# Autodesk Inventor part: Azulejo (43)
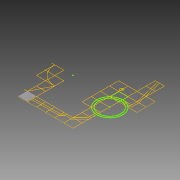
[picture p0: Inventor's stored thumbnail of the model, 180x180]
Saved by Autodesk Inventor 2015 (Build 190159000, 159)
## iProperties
Created: 2015-04
Part Number: Azulejo (43)
Material: Genérico
Document SubType Name: Modeling
Designer: Felipe
Density: 1 g/cm^3
Appearance: Padrão
Author: Felipe
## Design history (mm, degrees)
sketch "Sketch1"
  geometry: L1 (-1510, -7490)-(-1510, -6010); L2 (-3010, -1490)-(-3010, -10); L3 (-2990, 10)-(-1510, 10); L4 (-1510, -10)-(-2990, -10); L5 (-1510, -1490)-(-1510, -10); L6 (-1490, -10)-(-1490, -1490); L7 (-1490, -1490)-(-10, -1490); L8 (-10, -1510)-(-1490, -1510); L9 (-10, -2990)-(-10, -1510); L10 (-10, -5990)-(-10, -4510); L11 (-1490, -7490)-(-10, -7490); L12 (4490, -6010)-(3010, -6010); L13 (10, -1510)-(10, -2990); L14 (10, -3010)-(10, -4490); L15 (10, -4510)-(10, -5990); L16 (10, -5990)-(1490, -5990); L17 (1490, -6010)-(10, -6010); L18 (10, -7490)-(1490, -7490); L19 (1510, -5990)-(2990, -5990); L20 (2990, -6010)-(1510, -6010); L21 (1510, -7490)-(2990, -7490); L22 (4490, 1510)-(4490, 2990); L23 (4490, 10)-(4490, 1490); L24 (4490, -1490)-(4490, -10); L25 (4490, -2990)-(4490, -1510); L26 (3010, -5990)-(4490, -5990); L27 (3010, -7490)-(4490, -7490); L28 (4510, 3010)-(5990, 3010); L29 (5990, 2990)-(4510, 2990); L30 (4510, 2990)-(4510, 1510); L31 (4510, 1510)-(5990, 1510); L32 (5990, 1510)-(5990, 1740.185); L33 (5990, 1760.2)-(5990, 2259.8); L34 (5990, 2279.815)-(5990, 2990); L35 (5990, 1490)-(4510, 1490); L36 (4510, 1490)-(4510, 10); L37 (4510, 10)-(5990, 10); L38 (5990, 10)-(5990, 1490); L39 (5975.983, -10)-(4510, -10); L40 (4510, -10)-(4510, -1490); L41 (5990, -1510)-(5782.897, -1510); L42 (5782.897, -1510)-(5688.66, -1510); L43 (5668.66, -1510)-(5482.895, -1510); L44 (5482.895, -1510)-(5388.656, -1510); L45 (5368.656, -1510)-(4510, -1510); L46 (4510, -1510)-(4510, -2990); L47 (4510, -2990)-(5975.983, -2990); L48 (5990, -2975.728)-(5990, -2837.377); L49 (5990, -2837.377)-(5990, -2536.247); L50 (5990, -2500.476)-(5990, -2317.632); L51 (5990, -2317.632)-(5990, -1510); L52 (5990, -3010)-(4510, -3010); L53 (5990, -4490)-(5990, -3010); L54 (4510, -5990)-(5990, -5990); L55 (5990, -5990)-(5990, -4510); L56 (4510, -7490)-(5990, -7490); L57 (5990, -7490)-(5990, -6310); L58 (5990, -6290)-(5990, -6010); L59 (7490, 4510)-(7490, 5990); L60 (6010, 3010)-(7490, 3010); L61 (7490, 3010)-(7490, 4490); L62 (7490, 2990)-(6010, 2990); L63 (6010, 2990)-(6010, 2279.815); L64 (6010, 2259.8)-(6010, 1760.2)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; A1 r 250 centre (6000, 2010) between (5990, 2259.8) and (5990, 1760.2); A2 r 250 centre (6000, 2010) between (6010, 1760.2) and (6010, 2259.8); A3 r 270 centre (6000, 2010) between (5990, 2279.815) and (5990, 1740.185); A4 r 270 centre (6000, 2010) between (6010, 1740.185) and (6010, 2279.815); A5 r 3010.017 centre (0, 0) between (-1490, -2615.358) and (-346.554, -2990); A6 r 2990.017 centre (0, 0) between (-1490, -2592.316) and (-10, -2990); A7 r 3010.017 centre (0, 0) between (-2603.863, -1510) and (-1510, -2603.863); A8 r 2990.017 centre (0, 0) between (-2580.717, -1510) and (-1510, -2580.717); A9 r 3010.017 centre (0, 0) between (-2990, -346.554) and (-2615.358, -1490); A10 r 2990.017 centre (0, 0) between (-2990, -10) and (-2592.316, -1490); A11 r 2131.367 centre (7500, -1500) between (7490, 631.344) and (6010, 24.017); A12 r 2131.367 centre (7500, -1500) between (5975.983, -10) and (5368.656, -1490); A13 r 2131.367 centre (7500, -1500) between (5368.656, -1510) and (5975.983, -2990); A14 r 2131.367 centre (7500, -1500) between (6010, -3024.017) and (7190, -3608.703); A15 r 1831.367 centre (7500, -1500) between (7490.321, 331.342) and (6463.753, 10); A16 r 1831.367 centre (7500, -1500) between (7489.976, 331.34) and (6010, -435.196); A17 r 1831.367 centre (7500, -1500) between (5990, -463.753) and (5668.66, -1490); A18 r 1831.367 centre (7500, -1500) between (5668.66, -1510) and (5990, -2536.247); A19 r 1831.367 centre (7500, -1500) between (6010, -2564.804) and (6435.196, -2990); A20 r 1831.367 centre (7500, -1500) between (6463.753, -3010) and (7490, -3331.34); A21 r 2111.367 centre (7500, -1500) between (7490.389, 611.346) and (6024.272, 10); A22 r 2111.367 centre (7500, -1500) between (5990, -24.272) and (5388.656, -1490); A23 r 2111.367 centre (7500, -1500) between (5388.656, -1510) and (5990, -2975.728); A24 r 2111.367 centre (7500, -1500) between (6024.272, -3010) and (7210, -3591.357); A25 r 1811.367 centre (7499.986, -1499.91) between (7490.524, 311.432) and (6499.51, 10.09); A26 r 1811.367 centre (7500, -1500) between (6469.975, -10) and (6010, -469.975); A27 r 1811.367 centre (7500, -1500) between (5990, -499.524) and (5688.66, -1490); A28 r 1811.367 centre (7500, -1500) between (5688.66, -1510) and (5990, -2500.476); A29 r 1811.367 centre (7500, -1500) between (6010, -2530.025) and (6469.975, -2990); A30 r 1811.367 centre (7500, -1500) between (6499.524, -3010) and (7490, -3311.34); A31 r 449.871 centre (7499.449, -4060.672) between (7510, -4510.419) and (7521.546, -4510); A32 r 2111.367 centre (7500, -1500) between (7490.019, 611.344) and (7490.389, 611.346); A33 r 1831.367 centre (7500, -1500) between (7489.976, 331.34) and (7490.321, 331.342); A34 r 1811.367 centre (7499.986, -1499.91) between (7489.986, 311.429) and (7490.524, 311.432); A35 r 2131.367 centre (7500, -1500) between (7510, -3631.344) and (7190, -3608.703); A36 r 2131.367 centre (7500, -1500) between (7210, -3611.546) and (7490, -3631.344); 12 further points
  constraints: 718 end point, 82 point on circle, 36 centre point, 14 point on line, 3 concentric, 2 parallel, 2 perpendicular, 1 collinear, 1 horizontal, 1 vertical, 1 other
extrude "Extrusion1" new body sketch "Sketch1" distance "d0" = 60; taper "d1" = 0 deg
extrude "Extrusion2" new body sketch "Sketch1" distance "d2" = 60; taper "d3" = 0 deg
extrude "Extrusion3" new body sketch "Sketch1" distance "d4" = 60; taper "d5" = 0 deg
body "Solid1"
body "Solid2"
body "Solid3"
